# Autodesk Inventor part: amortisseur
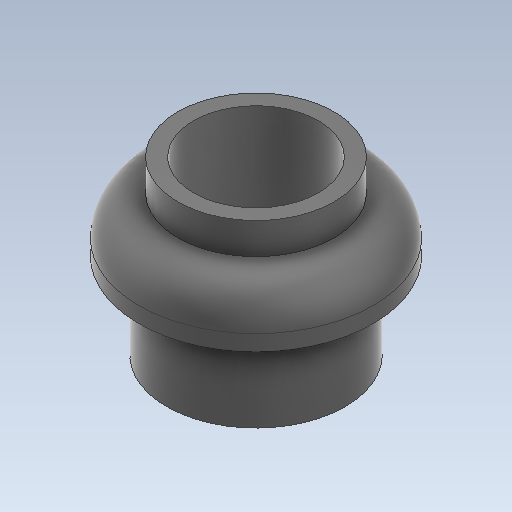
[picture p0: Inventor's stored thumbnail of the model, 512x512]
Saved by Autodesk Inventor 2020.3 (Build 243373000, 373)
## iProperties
Created: 2020-09
Part Number: amortisseur
Material: Résine acétal, noir
Document SubType Name: Modeling
Designer: ficho
Density: 1.425 g/cm^3
Appearance: Lisse - Noir
Mass: 1.03741 g
Surface Area: 9.01188 cm^2
Volume: 0.728006 cm^3
Author: ficho
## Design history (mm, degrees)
sketch "Esquisse1"
  geometry: L1 (4.039, 8.474)-(5, 8.474); L2 (7.5, 2.974)-(5.712, 2.974); L3 (5.712, 2.974)-(5.712, -2.526); L4 (5.712, -2.526)-(4, -2.526); L5 (4, -2.526)-(4, 8.474); L6 (4, 8.474)-(4.039, 8.474); L7 (7.5, 3.974)-(7.5, 2.974); L8 (5, 8.474)-(5, 6.474); L9 (0, -4.726)-(0, 10.674) reference; A1 r 2.5 centre (5, 3.974) between (7.5, 3.974) and (5, 6.474); 1 further point
  constraints: 16 end point, 2 parallel, 2 perpendicular, 2 point on circle, 2 point on line, 1 centre point, 1 collinear, 1 horizontal, 1 vertical
  dimensions: "d0" = 7.5 distance from line of L7 point (0, 0); "d1" = 4 distance from line of point (0, 0) L5; "d2" = 5 horizontal distance of L1.end point (0, 0); "d3" = 1 distance from line of A1.centre L2; "d4" = 2 distance from line of L8.end L1; "d5" = 5.5 distance between parallel lines of L4 L2
revolve "Révolution1" sketch "Esquisse1" stored, may be unused: angle "d6" = 90 deg
node "Solide1"
